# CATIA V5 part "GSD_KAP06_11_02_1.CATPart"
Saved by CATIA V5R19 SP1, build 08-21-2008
Part number: GSD_BLEND_02
Definition: Beispielmodell für Funktion Übergang / Blend - Schließpunkte.
Description: CATIA V5 Flächenmodellierung  Copyright (c) 2009 Maik Hertha IT Consultants
Bounding box of the stored display mesh (mm): x -83.184 to 84.357, y -79.412 to 63.099, z 10.158 to 100.578
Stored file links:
  \GSD_BUCH_UEBUNG\GSD_KAP06_11_02_1.CATPart
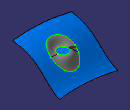
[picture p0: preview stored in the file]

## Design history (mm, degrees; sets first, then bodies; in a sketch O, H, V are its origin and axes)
AxisSystem1 "Absolute Axis System": origin (0, 0, 0), X (1, 0, 0), Y (0, 1, 0), Z (0, 0, 1)
Set1 "Blend Closing Points"
  Plane1: type Equation, A 1, B 0, C 0, Length 10
  Plane2: type Equation, A 0, B 1, C 0, Length 10
  Sketch1 on Plane1, origin (10, 0, 0), H (0, 1, 0), V (0, 0, 1)
    spline S1 through (-65.2612, 78.1032) (-9.8286, 51.5504) (16.7565, 27.5399) (69.3609, -3.2501)
  Sketch2 on Plane2, origin (0, 10, 0), H (-1, 0, 0), V (0, 0, 1)
    spline S1 through (-84.3573, 57.652) (-27.1326, 60.1922) (83.1839, 48.4436)
  Sweep1: type Unspec, Guide Sketch1, Profile Sketch2
  Plane3: type Equation, A 0, B 0, C 1, Length 10
  Point1: type OnPlane, Support Plane3, Direction (1, 0, 0), H 10, V -5
  Project1: Support Sweep1, Direction (0, 0, 1), ToProject Point1
  Plane4: type OffsetPt, RefPlane Plane3, RefPoint Project1
  Sketch3 on Plane4, origin (10, -5, 73.0975), H (-1, 0, 0), V (0, -1, 0)
    circle A1 centre (0, 0) radius 15
    point P1 (0, 0)
    construction line L1 (0, 50.1877) -> (0, -40.9217)
    construction line L2 (-38.9266, 0) -> (47.295, 0)
    reference projected point E1 (0, 0) from Point1
    radius A1 = 15
    vertical: L1 V
    horizontal: L2 H
    coincidence: P1 L1, P1 L2, E1 P1
  Split1: ToCut Plane4, Intersections {intersect ToIntersect1 Plane4, ToIntersect2 Sketch3}, Cutting Sketch3
  Extrude1: Lim1 40, Lim2 50, Element1 {intersect ToIntersect1 Plane4, ToIntersect2 Sketch3}, Direction Plane4
  Offset1: Length 20, Offset Extrude1
  Split2: ToCut Sweep1, Intersections {intersect ToIntersect1 Sweep1, ToIntersect2 Offset1}, Cutting Offset1
  Blend1: StartLimit {blendlimit Support Split1, Curve {intersect ToIntersect1 Plane4, ToIntersect2 Sketch3}, Point {extremum Reference {intersect ToIntersect1 Plane4, ToIntersect2 Sketch3}, Direction2 (0, 0, 1), Direction3 (0, 0, 1), Direction (1, 0, 0)}}, EndLimit {blendlimit Support Split2, Curve {intersect ToIntersect1 Sweep1, ToIntersect2 Offset1}, Point {extremum Reference {intersect ToIntersect1 Sweep1, ToIntersect2 Offset1}, Direction2 (0, 0, 1), Direction3 (0, 0, 1), Direction (1, 0, 0)}}
Body1 (main body)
